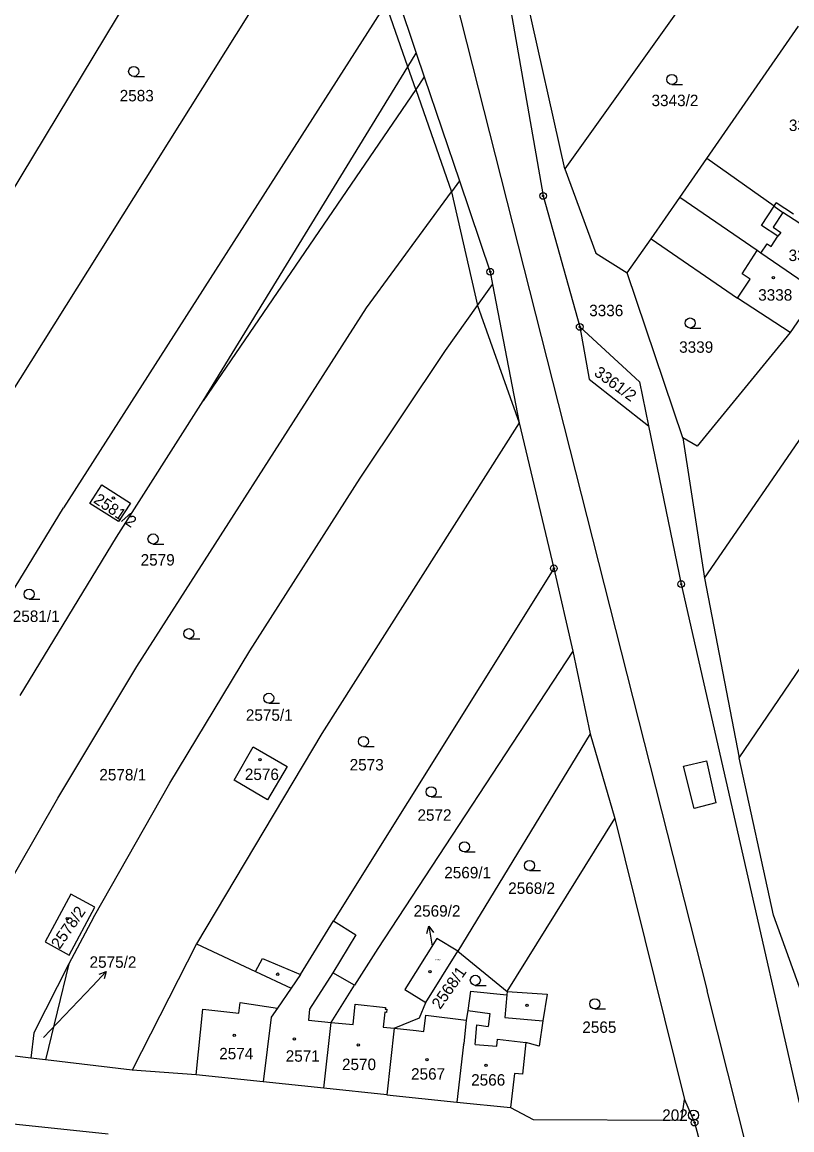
# Model space of a CAD drawing. Extents: x -755819 to -753140, y -1169796 to -1166000.
# Drawn here: x -754494.4 to -754380.1, y -1168949.3 to -1168784.9 of the extents above; entities that cross this region are included whole.
import ezdxf

# ---------------------------------------------------------------- set-up
doc = ezdxf.new("R2010")
doc.units = 0
for name, color, linetype in [('Vrstva 1', 7, 'Continuous'), ('Vrstva 10', 7, 'Continuous'), ('Vrstva 16', 7, 'Continuous'), ('Vrstva 17', 7, 'Continuous'), ('Vrstva 18', 7, 'Continuous'), ('Vrstva 19', 7, 'Continuous'), ('Vrstva 24', 7, 'Continuous'), ('Vrstva 25', 7, 'Continuous'), ('Vrstva 4', 7, 'Continuous'), ('Vrstva 6', 7, 'Continuous')]:
    doc.layers.add(name, color=color, linetype=linetype)

msp = doc.modelspace()

# ---------------------------------------------------------------- linework, layer by layer
at = {"layer": 'Vrstva 1'}
for p, q in [((-754451.95, -1168737.18), (-754516.29, -1168843.7)), ((-754502.8, -1168850.81), (-754446.52, -1168760.99)), ((-754413.83, -1168806.63), (-754421.93, -1168770.23)), ((-754423.83, -1168771.88), (-754417.05, -1168810.66)), ((-754389.49, -1168772.51), (-754413.83, -1168806.63)), ((-754439.11, -1168779.87), (-754435.88, -1168789.44)), ((-754440.39, -1168782.12), (-754488.24, -1168856.95)), ((-754392.76, -1168805.11), (-754379.13, -1168785.43)), ((-754435.88, -1168789.44), (-754434.68, -1168792.97)), ((-754434.68, -1168792.97), (-754429.46, -1168808.42)), ((-754396.75, -1168810.87), (-754392.76, -1168805.11)), ((-754382.78, -1168812.18), (-754392.76, -1168805.11)), ((-754413.83, -1168806.63), (-754409.23, -1168819.18)), ((-754429.46, -1168808.42), (-754430.65, -1168810.04)), ((-754429.46, -1168808.42), (-754424.9, -1168821.92)), ((-754443.28, -1168827.28), (-754430.65, -1168810.04)), ((-754417.05, -1168810.66), (-754411.61, -1168830.11)), ((-754401.03, -1168817.01), (-754396.75, -1168810.87)), ((-754385.26, -1168818.77), (-754396.75, -1168810.87)), ((-754382.78, -1168812.18), (-754381.45, -1168813.11)), ((-754372.41, -1168819.08), (-754381.45, -1168813.11)), ((-754404.58, -1168822.1), (-754401.03, -1168817.01)), ((-754401.03, -1168817.01), (-754388.18, -1168825.84)), ((-754409.23, -1168819.18), (-754404.58, -1168822.1)), ((-754384.72, -1168819.14), (-754385.26, -1168818.77)), ((-754376.28, -1168824.95), (-754384.72, -1168819.14)), ((-754424.9, -1168821.92), (-754424.54, -1168823.8)), ((-754396.3, -1168846.57), (-754404.58, -1168822.1)), ((-754426.79, -1168826.94), (-754424.54, -1168823.8)), ((-754424.54, -1168823.8), (-754420.6, -1168844.33)), ((-754380.38, -1168830.94), (-754388.18, -1168825.84)), ((-754376.28, -1168824.95), (-754380.38, -1168830.94)), ((-754477.37, -1168880.54), (-754443.28, -1168827.28)), ((-754431.55, -1168833.59), (-754426.79, -1168826.94)), ((-754411.61, -1168830.11), (-754402.76, -1168838.28)), ((-754380.38, -1168830.94), (-754394.21, -1168847.82)), ((-754444.22, -1168852.55), (-754431.55, -1168833.59)), ((-754402.76, -1168838.28), (-754401.41, -1168844.82)), ((-754393.12, -1168867.44), (-754373.15, -1168838.34)), ((-754480.34, -1168861.35), (-754467.51, -1168841.1)), ((-754420.6, -1168844.33), (-754449.89, -1168890.49)), ((-754420.6, -1168844.33), (-754415.45, -1168865.96)), ((-754401.41, -1168844.82), (-754396.56, -1168868.29)), ((-754394.21, -1168847.82), (-754396.3, -1168846.57)), ((-754396.3, -1168846.57), (-754393.12, -1168867.44)), ((-754460.56, -1168878.23), (-754444.22, -1168852.55)), ((-754484.32, -1168856.31), (-754482.56, -1168853.56)), ((-754482.56, -1168853.56), (-754478.3, -1168856.26)), ((-754499.2, -1168874.96), (-754488.24, -1168856.95)), ((-754480.05, -1168859.02), (-754484.32, -1168856.31)), ((-754478.3, -1168856.26), (-754480.05, -1168859.02)), ((-754494.64, -1168884.83), (-754480.34, -1168861.35)), ((-754415.45, -1168865.96), (-754448.17, -1168918.32)), ((-754415.45, -1168865.96), (-754412.65, -1168878.24)), ((-754396.56, -1168868.29), (-754379.05, -1168945.33)), ((-754393.12, -1168867.44), (-754387.93, -1168894.11)), ((-754472.47, -1168897.88), (-754460.56, -1168878.23)), ((-754412.65, -1168878.24), (-754441.58, -1168922.39)), ((-754412.65, -1168878.24), (-754410.06, -1168890.53)), ((-754387.93, -1168894.11), (-754378.72, -1168880.46)), ((-754489.07, -1168900.09), (-754477.37, -1168880.54)), ((-754449.89, -1168890.49), (-754468.49, -1168921.69)), ((-754410.06, -1168890.53), (-754429.73, -1168922.78)), ((-754410.06, -1168890.53), (-754406.43, -1168903.09)), ((-754462.92, -1168897.4), (-754460.07, -1168892.45)), ((-754460.07, -1168892.45), (-754455.03, -1168895.36)), ((-754382.87, -1168917.47), (-754387.93, -1168894.11)), ((-754455.03, -1168895.36), (-754457.95, -1168900.33)), ((-754483.78, -1168917.79), (-754472.47, -1168897.88)), ((-754457.95, -1168900.33), (-754462.92, -1168897.4)), ((-754498.86, -1168917.13), (-754489.07, -1168900.09)), ((-754422.39, -1168928.77), (-754406.43, -1168903.09)), ((-754406.43, -1168903.09), (-754396.05, -1168944.82)), ((-754487.14, -1168914.36), (-754490.93, -1168921.44)), ((-754483.59, -1168916.28), (-754487.14, -1168914.36)), ((-754487.4, -1168923.38), (-754483.59, -1168916.28)), ((-754483.78, -1168917.79), (-754487.43, -1168924.67)), ((-754453.08, -1168926.28), (-754448.17, -1168918.32)), ((-754448.17, -1168918.32), (-754444.86, -1168920.39)), ((-754378.13, -1168930.64), (-754382.87, -1168917.47)), ((-754490.93, -1168921.44), (-754487.4, -1168923.38)), ((-754444.86, -1168920.39), (-754448.28, -1168926)), ((-754432.81, -1168920.9), (-754437.59, -1168928.48)), ((-754429.73, -1168922.78), (-754432.81, -1168920.9)), ((-754468.49, -1168921.69), (-754478.02, -1168940.49)), ((-754468.49, -1168921.69), (-754459.74, -1168925.82)), ((-754441.58, -1168922.39), (-754445.02, -1168927.83)), ((-754434.48, -1168930.44), (-754429.73, -1168922.78)), ((-754429.73, -1168922.78), (-754422.39, -1168928.77)), ((-754487.43, -1168924.67), (-754492.64, -1168934.93)), ((-754487.43, -1168924.67), (-754490.91, -1168938.93)), ((-754459.74, -1168925.82), (-754458.72, -1168923.88)), ((-754458.72, -1168923.88), (-754453.08, -1168926.28)), ((-754453.08, -1168926.28), (-754454.46, -1168928.29)), ((-754445.02, -1168927.83), (-754448.28, -1168926)), ((-754448.49, -1168933.38), (-754445.02, -1168927.83)), ((-754454.46, -1168928.29), (-754456.49, -1168931.25)), ((-754437.59, -1168928.48), (-754434.48, -1168930.44)), ((-754427.85, -1168928.75), (-754428.24, -1168931.61)), ((-754427.85, -1168928.75), (-754422.44, -1168929.31)), ((-754422.39, -1168928.77), (-754422.44, -1168929.31)), ((-754422.39, -1168928.77), (-754416.46, -1168929.19)), ((-754416.46, -1168929.19), (-754417.07, -1168933.14)), ((-754456.49, -1168931.25), (-754457.42, -1168932.6)), ((-754445.25, -1168933.67), (-754444.92, -1168930.69)), ((-754444.92, -1168930.69), (-754440.44, -1168931.16)), ((-754440.44, -1168931.16), (-754440.47, -1168931.4)), ((-754440.47, -1168931.4), (-754440.26, -1168931.42)), ((-754440.26, -1168931.42), (-754440.31, -1168931.89)), ((-754435.41, -1168932.72), (-754434.48, -1168930.44)), ((-754457.42, -1168932.6), (-754458.62, -1168942.21)), ((-754440.52, -1168931.87), (-754440.77, -1168934.08)), ((-754440.31, -1168931.89), (-754440.52, -1168931.87)), ((-754439.14, -1168934.23), (-754435.41, -1168932.72)), ((-754434.76, -1168934.72), (-754434.48, -1168932.33)), ((-754434.48, -1168932.33), (-754428.45, -1168933.04)), ((-754428.45, -1168933.04), (-754428.84, -1168936.55)), ((-754428.24, -1168931.61), (-754428.45, -1168933.04)), ((-754417.07, -1168933.14), (-754417.65, -1168936.92)), ((-754449.57, -1168943.16), (-754448.49, -1168933.38)), ((-754448.49, -1168933.38), (-754445.25, -1168933.67)), ((-754440.77, -1168934.08), (-754439.14, -1168934.23)), ((-754439.14, -1168934.23), (-754440.24, -1168944.14)), ((-754439.14, -1168934.23), (-754435.9, -1168934.59)), ((-754435.9, -1168934.59), (-754434.76, -1168934.72)), ((-754492.64, -1168934.93), (-754493.09, -1168938.67)), ((-754419.59, -1168936.35), (-754420.13, -1168941.08)), ((-754417.65, -1168936.92), (-754419.59, -1168936.35)), ((-754428.86, -1168936.68), (-754429.85, -1168945.24)), ((-754428.86, -1168936.68), (-754428.84, -1168936.55)), ((-754493.09, -1168938.67), (-754495.85, -1168938.33)), ((-754490.91, -1168938.93), (-754493.09, -1168938.67)), ((-754478.02, -1168940.49), (-754490.91, -1168938.93)), ((-754468.53, -1168941.18), (-754478.02, -1168940.49)), ((-754458.62, -1168942.21), (-754468.53, -1168941.18)), ((-754421.31, -1168940.95), (-754421.89, -1168946.03)), ((-754420.13, -1168941.08), (-754421.31, -1168940.95)), ((-754449.57, -1168943.16), (-754458.62, -1168942.21)), ((-754440.24, -1168944.14), (-754449.57, -1168943.16)), ((-754440.24, -1168944.14), (-754429.85, -1168945.24)), ((-754429.85, -1168945.24), (-754421.89, -1168946.03)), ((-754421.89, -1168946.03), (-754418.54, -1168947.81)), ((-754396.5, -1168947.91), (-754396.05, -1168944.82)), ((-754396.05, -1168944.82), (-754394.57, -1168948.26)), ((-754507.06, -1168947.27), (-754481.59, -1168949.91)), ((-754418.54, -1168947.81), (-754396.5, -1168947.91)), ((-754394.57, -1168948.26), (-754386.06, -1168980.52))]:
    msp.add_line(p, q, dxfattribs=at)
at = {"layer": 'Vrstva 10'}
for p in [(-754525.56, -1168404.38), (-754346.69, -1169111.14)]:
    msp.add_line(p, (-754392.72, -1168928.69), dxfattribs=at)
at = {"layer": 'Vrstva 16'}
for p, q in [((-754434, -1168919.1), (-754433.5, -1168922.06)), ((-754481.88, -1168925.82), (-754483.95, -1168927.99)), ((-754491.22, -1168935.61), (-754483.95, -1168927.99))]:
    msp.add_line(p, q, dxfattribs=at)
for points in [[(-754434.33, -1168920.17), (-754434, -1168919.1), (-754433.34, -1168920.01)], [(-754482.93, -1168926.2), (-754481.88, -1168925.82), (-754482.21, -1168926.89)]]:
    msp.add_lwpolyline(points, dxfattribs=at)
at = {"layer": 'Vrstva 24'}
for centre, radius in [((-754417.05, -1168810.66), 0.5), ((-754417.05, -1168810.66), 0.1), ((-754424.9, -1168821.92), 0.5), ((-754424.9, -1168821.92), 0.1), ((-754411.61, -1168830.11), 0.5), ((-754411.61, -1168830.11), 0.1), ((-754415.45, -1168865.96), 0.5), ((-754415.45, -1168865.96), 0.1), ((-754396.56, -1168868.29), 0.5), ((-754396.56, -1168868.29), 0.1), ((-754394.72, -1168947.15), 0.75), ((-754394.57, -1168948.26), 0.5), ((-754394.72, -1168947.15), 0.1), ((-754394.57, -1168948.26), 0.1)]:
    msp.add_circle(centre, radius, dxfattribs=at)
at = {"layer": 'Vrstva 25'}
for p, q in [((-754477.81, -1168792.92), (-754476.21, -1168792.92)), ((-754397.95, -1168794.11), (-754396.35, -1168794.11)), ((-754395.22, -1168830.28), (-754393.62, -1168830.28)), ((-754474.94, -1168862.35), (-754473.34, -1168862.35)), ((-754493.34, -1168870.54), (-754491.74, -1168870.54)), ((-754469.62, -1168876.41), (-754468.02, -1168876.41)), ((-754457.77, -1168886), (-754456.17, -1168886)), ((-754443.72, -1168892.41), (-754442.12, -1168892.41)), ((-754433.67, -1168899.89), (-754432.07, -1168899.89)), ((-754428.73, -1168908.07), (-754427.13, -1168908.07)), ((-754419.06, -1168910.83), (-754417.46, -1168910.83)), ((-754427.11, -1168927.88), (-754425.51, -1168927.88)), ((-754409.38, -1168931.38), (-754407.78, -1168931.38))]:
    msp.add_line(p, q, dxfattribs=at)
for centre, radius in [((-754477.81, -1168792.17), 0.75), ((-754397.95, -1168793.36), 0.75), ((-754382.88, -1168822.78), 0.175), ((-754395.22, -1168829.53), 0.75), ((-754480.81, -1168855.5), 0.175), ((-754474.94, -1168861.6), 0.75), ((-754493.34, -1168869.79), 0.75), ((-754469.62, -1168875.66), 0.75), ((-754457.77, -1168885.25), 0.75), ((-754443.72, -1168891.66), 0.75), ((-754459.09, -1168894.37), 0.175), ((-754433.67, -1168899.14), 0.75), ((-754428.73, -1168907.32), 0.75), ((-754419.06, -1168910.08), 0.75), ((-754487.67, -1168918), 0.175), ((-754456.44, -1168926.22), 0.175), ((-754433.86, -1168925.87), 0.175), ((-754427.11, -1168927.13), 0.75), ((-754419.44, -1168930.85), 0.175), ((-754409.38, -1168930.63), 0.75), ((-754462.89, -1168935.3), 0.175), ((-754453.97, -1168935.83), 0.175), ((-754444.48, -1168936.72), 0.175), ((-754434.3, -1168938.91), 0.175), ((-754425.51, -1168939.75), 0.175)]:
    msp.add_circle(centre, radius, dxfattribs=at)
at = {"layer": 'Vrstva 4'}
for p, q in [((-754437.13, -1168791.48), (-754440.39, -1168782.12)), ((-754435.96, -1168794.84), (-754437.13, -1168791.48)), ((-754434.68, -1168792.97), (-754435.96, -1168794.84)), ((-754435.96, -1168794.84), (-754467.51, -1168841.1)), ((-754435.96, -1168794.84), (-754430.65, -1168810.04)), ((-754430.65, -1168810.04), (-754426.79, -1168826.94)), ((-754384.64, -1168815.03), (-754382.78, -1168812.18)), ((-754382.78, -1168812.18), (-754382.46, -1168811.69)), ((-754379.91, -1168813.36), (-754382.46, -1168811.69)), ((-754381.45, -1168813.11), (-754382.93, -1168815.28)), ((-754382.2, -1168816.65), (-754384.64, -1168815.03)), ((-754382.93, -1168815.28), (-754381.77, -1168816.07)), ((-754381.77, -1168816.07), (-754382.2, -1168816.65)), ((-754384.72, -1168819.14), (-754383.81, -1168817.76)), ((-754383.81, -1168817.76), (-754383.19, -1168818.16)), ((-754383.19, -1168818.16), (-754382.2, -1168816.65)), ((-754387.51, -1168822.22), (-754385.26, -1168818.77)), ((-754386.32, -1168823), (-754387.51, -1168822.22)), ((-754388.18, -1168825.84), (-754386.32, -1168823)), ((-754426.79, -1168826.94), (-754420.6, -1168844.33)), ((-754396.22, -1168895.33), (-754392.79, -1168894.53)), ((-754394.61, -1168901.6), (-754396.22, -1168895.33)), ((-754392.79, -1168894.53), (-754391.44, -1168900.79)), ((-754391.44, -1168900.79), (-754394.61, -1168901.6)), ((-754459.74, -1168925.82), (-754454.46, -1168928.29)), ((-754448.28, -1168926), (-754451.73, -1168931.44)), ((-754422.44, -1168929.31), (-754422.75, -1168932.64)), ((-754468.53, -1168941.18), (-754467.54, -1168931.41)), ((-754467.54, -1168931.41), (-754462.19, -1168931.99)), ((-754462.19, -1168931.99), (-754462.02, -1168930.44)), ((-754462.02, -1168930.44), (-754456.49, -1168931.25)), ((-754451.73, -1168931.44), (-754451.89, -1168933.04)), ((-754451.89, -1168933.04), (-754448.49, -1168933.38)), ((-754428.24, -1168931.61), (-754424.95, -1168932.04)), ((-754424.95, -1168932.04), (-754425.19, -1168934)), ((-754422.75, -1168932.64), (-754417.07, -1168933.14)), ((-754427.12, -1168936.68), (-754426.91, -1168933.76)), ((-754426.91, -1168933.76), (-754425.19, -1168934)), ((-754423.92, -1168936.91), (-754423.8, -1168935.86)), ((-754423.8, -1168935.86), (-754419.59, -1168936.35)), ((-754427.12, -1168936.68), (-754423.92, -1168936.91))]:
    msp.add_line(p, q, dxfattribs=at)
at = {"layer": 'Vrstva 6'}
for p, q in [((-754437.13, -1168791.48), (-754435.88, -1168789.44)), ((-754467.51, -1168841.1), (-754437.13, -1168791.48)), ((-754411.61, -1168830.11), (-754410.22, -1168837.85)), ((-754410.22, -1168837.85), (-754401.41, -1168844.82))]:
    msp.add_line(p, q, dxfattribs=at)

# ---------------------------------------------------------------- texts
at = {"layer": 'Vrstva 16'}
for s, p in [('2569/2', (-754436.27, -1168917.68)), ('2575/2', (-754484.36, -1168925.27))]:
    msp.add_text(s, height=1.7, dxfattribs=at).set_placement(p)
at = {"layer": 'Vrstva 17'}
msp.add_text('202', height=1.7, dxfattribs=at).set_placement((-754399.37, -1168948))
at = {"layer": 'Vrstva 18'}
for s, height, p in [('2583', 1.7, (-754479.89, -1168796.62)), ('3343/2', 1.7, (-754400.96, -1168797.33)), ('3341/1', 1.7, (-754380.58, -1168801.02)), ('3336', 1.7, (-754410.21, -1168828.52)), ('3339', 1.7, (-754396.86, -1168833.95)), ('2579', 1.7, (-754476.78, -1168865.55)), ('2581/1', 1.7, (-754495.76, -1168873.92)), ('2575/1', 1.7, (-754461.17, -1168888.59)), ('2573', 1.7, (-754445.76, -1168895.97)), ('2578/1', 1.7, (-754482.91, -1168897.45)), ('2572', 1.7, (-754435.7, -1168903.44)), ('2569/1', 1.7, (-754431.72, -1168911.99)), ('2568/2', 1.7, (-754422.23, -1168914.3)), ('2565', 1.7, (-754411.23, -1168934.94)), ('2575/2', 0.1, (-754491.47, -1168935.61))]:
    msp.add_text(s, height=height, dxfattribs=at).set_placement(p)
for s, rotation, p in [('3361/2', 324.0076, (-754409.62, -1168837.2)), ('2568/1', 54.8894, (-754432.33, -1168931.55))]:
    msp.add_text(s, height=1.7, rotation=rotation, dxfattribs=at).set_placement(p)
at = {"layer": 'Vrstva 19'}
for s, height, p in [('3340', 1.7, (-754380.62, -1168820.33)), ('3338', 1.7, (-754385.13, -1168826.21)), ('2576', 1.7, (-754461.32, -1168897.39)), ('2569/2', 0.2, (-754433.12, -1168924.18)), ('2574', 1.7, (-754465.12, -1168938.86)), ('2571', 1.7, (-754455.25, -1168939.22)), ('2570', 1.7, (-754446.9, -1168940.46)), ('2567', 1.7, (-754436.65, -1168941.88)), ('2566', 1.7, (-754427.73, -1168942.77))]:
    msp.add_text(s, height=height, dxfattribs=at).set_placement(p)
for s, rotation, p in [('2581/2', 325.8984, (-754483.89, -1168856.11)), ('2578/2', 55.2904, (-754488.81, -1168922.62))]:
    msp.add_text(s, height=1.7, rotation=rotation, dxfattribs=at).set_placement(p)

doc.saveas('drawing.dxf')
